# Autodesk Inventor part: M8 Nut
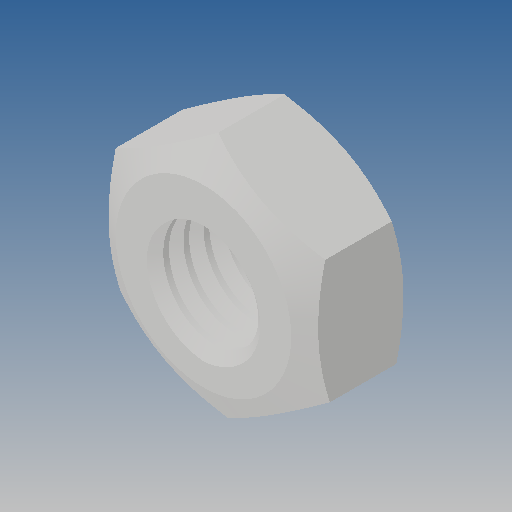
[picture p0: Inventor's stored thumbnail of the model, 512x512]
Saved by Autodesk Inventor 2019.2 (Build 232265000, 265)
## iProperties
Created: 2012-09
Part Number: M8 Nut
Material: Ogólny
Document SubType Name: Modeling
Designer: CADENGINEERING4
Density: 1 g/cm^3
Appearance: Domyślna
Author: CADENGINEERING4
Revision Number: ÈÎºÎ
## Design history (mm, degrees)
feature "ÇÐ³ý-É¨Ãè1"
node "Bryła1"
